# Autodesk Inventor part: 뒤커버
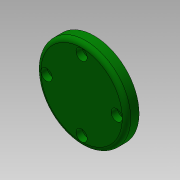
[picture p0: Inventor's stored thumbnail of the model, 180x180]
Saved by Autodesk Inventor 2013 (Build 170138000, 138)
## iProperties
Created: 2019-01
Part Number: 뒤커버
Material: 알루미늄 6061
Document SubType Name: Modeling
Designer: mduedu
Density: 2.40731 g/cm^3
Mass: 65.0186 g
Surface Area: 93.0687 cm^2
Volume: 27.0088 cm^3
Author: mduedu
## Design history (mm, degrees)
sketch "스케치1"
  geometry: L1 (0, 0)-(9, 0); L2 (9, 0)-(9, 32); L3 (9, 32)-(0, 32); L4 (0, 32)-(0, 0); L5 (9, 0)-(12, 0); L6 (12, 0)-(12, 20); L7 (12, 20)-(9, 20); L8 (9, 20)-(9, 0)
  constraints: 16 end point, 4 parallel, 2 horizontal, 2 perpendicular
  dimensions: "d0" = 12 distance between parallel lines of L6 L4; "d2" = 64 diameter of L3 L1; "d3" = 40 diameter of L7 L5; "d4" = 3 distance between parallel lines of L6 L2
revolve "회전1" sketch "스케치1" stored, may be unused: angle "d5" = 90 deg
sketch "스케치4"
  geometry: C1 r 15 at (0, 0); 1 further point
  constraints: 1 centre point, 1 coincident
  dimensions: "d24" = 30 diameter of C1
extrude "돌출1" cut sketch "스케치4" distance "d25" = 6; taper "d26" = 0 deg
fillet "모깎기4" dims "d27" = 3
fillet "모깎기3" dims "d18" = 3
chamfer "모따기2" distance "d28" = 1; stored, may be unused: second distance "d29" = 2, angle "d30" = 45 deg
sketch "스케치3" dims "d19" = 50
  geometry: 6 further points
  constraints: 2 vertical alignment, 1 coincident, 7 other
  dimensions: "d22" = 360 deg dimension on point (0, 0) point (0, 25) (derived)
sketch "스케치5"
  geometry: 4 further points
  constraints: 4 other
hole "구멍1" sketch "스케치5" at (-25, 0), (0, -25), (25, 0), (0, 25) diameter "d31" = 4.5; stored, may be unused: countersink angle "d35" = 90 deg, drill point angle "d37" = 0 deg; dims "d32" = 6, "d33" = 8, "d34" = 4.6, "d36" = 8
node "솔리드1"
